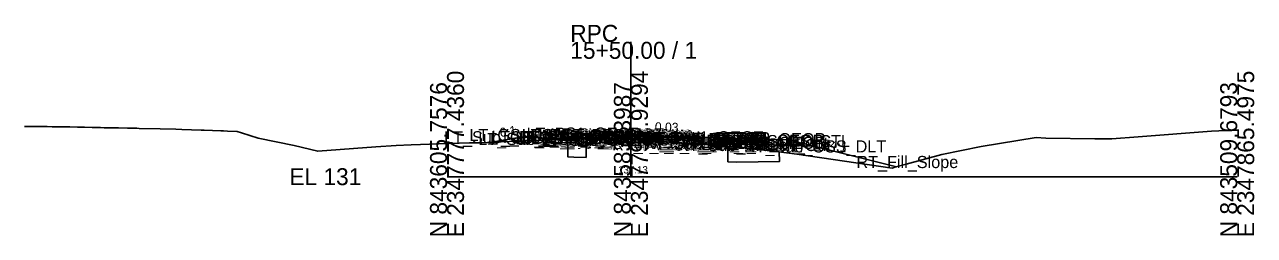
# Model space of a CAD drawing. Extents: x -26 to 203, y -10 to 7538.
# Drawn here: x 0 to 202.8, y 1990.3 to 2025.1 of the extents above; entities that cross this region are included whole.
import ezdxf

# ---------------------------------------------------------------- set-up
doc = ezdxf.new("R2010")
doc.units = 0
for name, color, linetype in [('Default', 7, 'Continuous'), ('Exist CMT Pavement', 7, 'Continuous'), ('Exist Cross Section Cell', 7, 'Continuous'), ('Exist XS Center Line Elevation Label', 7, 'Continuous'), ('Exist XS Ground Line', 7, 'Continuous'), ('Prop CMT Pvmt Course 1', 7, 'Continuous'), ('Prop CMT Pvmt Course 1 Wedge', 7, 'Continuous'), ('Prop CMT Pvmt Course 2', 7, 'Continuous'), ('Prop CMT Pvmt Course 2 Wedge', 7, 'Continuous'), ('Prop CMT Pvmt Course 3', 7, 'Continuous'), ('Prop CMT Pvmt Course 3 Wedge', 7, 'Continuous'), ('Prop CMT Pvmt Surface', 7, 'Continuous'), ('Prop CMT Pvmt Surface Shoulder', 7, 'Continuous'), ('Prop CMT Pvmt Wedge Surface 1', 7, 'Continuous'), ('Prop CMT Pvmt Wedge Surface 2', 7, 'Continuous'), ('Prop CMT Pvmt Wedge Surface 3', 7, 'Continuous'), ('Prop CMT Shld Paved Course 1', 7, 'Continuous'), ('Prop CMT Shld Paved Course 2', 7, 'Continuous'), ('Prop CMT Shld Paved Course 3', 7, 'Continuous'), ('Prop CMT Slope Grass', 7, 'Continuous'), ('Prop CMT Subgrade Earthwork', 7, 'Continuous'), ('Prop Road Sect_ Recs - UC (Outline)', 7, 'Continuous'), ('Prop XS Earthwork Shape', 7, 'Continuous'), ('Prop XS SE Text', 7, 'Continuous'), ('Prop XS Side Slope Text', 7, 'Continuous'), ('Scratch_Level_0', 7, 'Continuous')]:
    doc.layers.add(name, color=color, linetype=linetype)

msp = doc.modelspace()

# ---------------------------------------------------------------- linework, layer by layer
at = {"layer": 'Exist CMT Pavement'}
for q in [(96, 2006.36), (112, 2005.32)]:
    msp.add_line((100, 2006.13), q, dxfattribs=at)
at = {"layer": 'Exist Cross Section Cell'}
for p, q in [((100, 2000), (100, 2022.25)), ((69.67, 2000), (100, 2000)), ((100, 2000), (200, 2000))]:
    msp.add_line(p, q, dxfattribs=at)
at = {"layer": 'Exist XS Ground Line'}
msp.add_lwpolyline([(0, 2008.27), (1.96, 2008.27), (2.8, 2008.27), (3.74, 2008.26), (4.57, 2008.25), (5.33, 2008.24), (6.34, 2008.23), (7.44, 2008.21), (8.75, 2008.18), (9.89, 2008.16), (11.15, 2008.14), (12.5, 2008.09), (13.11, 2008.08), (14.77, 2008.05), (15.15, 2008.04), (15.5, 2008.04), (16.95, 2008.01), (18.52, 2007.98), (18.91, 2007.97), (22.34, 2007.89), (24.93, 2007.83), (25.94, 2007.77), (29.12, 2007.68), (29.61, 2007.66), (32.38, 2007.56), (32.82, 2007.55), (33.44, 2007.5), (35.08, 2007.44), (35.76, 2007.23), (38.55, 2006.36), (44.44, 2005.15), (48.34, 2004.2), (57.91, 2004.91), (61.27, 2005.16), (63.74, 2005.24), (68.35, 2005.43), (73.39, 2005.57), (75.43, 2005.61), (77.3, 2005.68), (86.68, 2006.1), (92.61, 2006.35), (92.97, 2006.35), (93.53, 2006.36), (95.69, 2006.38), (96.47, 2006.33), (96.89, 2006.3), (98.35, 2006.23), (100.26, 2006.12), (103.66, 2005.9), (105.46, 2005.78), (107.09, 2005.66), (107.43, 2005.63), (110.45, 2005.41), (110.97, 2005.38), (112.28, 2005.3), (113.86, 2005.16), (114.27, 2005.13), (115.26, 2005.11), (115.92, 2005.06), (121.74, 2004.41), (123.95, 2004.16), (127.38, 2003.69), (143.07, 2001.4), (143.7, 2001.6), (145.4, 2002.05), (151.3, 2003.68), (157.75, 2004.96), (166.86, 2006.47), (168.43, 2006.36), (176.52, 2006.24), (178.64, 2006.23), (179.3, 2006.26), (183.69, 2006.55), (195.76, 2007.5), (199.39, 2007.66), (200, 2007.7)], dxfattribs=at)
at = {"layer": 'Prop CMT Pvmt Course 1'}
for p, q in [((100, 2006.86), (96, 2006.98)), ((96, 2006.98), (96, 2006.73)), ((96, 2006.73), (96, 2006.86)), ((96, 2006.86), (100, 2006.74)), ((96, 2006.73), (96, 2006.73)), ((100, 2006.61), (100, 2006.86)), ((100, 2006.86), (112, 2006.5)), ((100, 2006.61), (100, 2006.86)), ((100, 2006.74), (100, 2006.61)), ((112, 2006.37), (100, 2006.74)), ((100, 2006.74), (100, 2006.61)), ((100, 2006.61), (100, 2006.61)), ((100, 2006.61), (100, 2006.61)), ((112, 2006.5), (112, 2006.25)), ((112, 2006.25), (112, 2006.37)), ((112, 2006.25), (112, 2006.25))]:
    msp.add_line(p, q, dxfattribs=at)
at = {"layer": 'Prop CMT Pvmt Course 1 Wedge'}
for q in [(96, 2006.86), (112, 2006.37)]:
    msp.add_line((100, 2006.74), q, dxfattribs=at)
at = {"layer": 'Prop CMT Pvmt Course 2'}
for p, q in [((96, 2006.4), (96, 2006.73)), ((96, 2006.73), (96, 2006.73)), ((96, 2006.73), (96, 2006.4)), ((96, 2006.4), (96, 2006.4)), ((112, 2005.91), (112, 2006.25)), ((112, 2006.25), (112, 2006.25)), ((112, 2006.25), (112, 2005.91)), ((112, 2005.91), (112, 2005.91))]:
    msp.add_line(p, q, dxfattribs=at)
at = {"layer": 'Prop CMT Pvmt Course 2 Wedge'}
for q in [(96, 2006.73), (112, 2006.25)]:
    msp.add_line((100, 2006.61), q, dxfattribs=at)
at = {"layer": 'Prop CMT Pvmt Course 3'}
for p, q in [((96, 2006.4), (96, 2006.4)), ((96, 2006.4), (96, 2006.07)), ((96, 2006.07), (96, 2006.4)), ((96, 2006.07), (96, 2006.07)), ((112, 2005.91), (112, 2005.91)), ((112, 2005.91), (112, 2005.58)), ((112, 2005.58), (112, 2005.91)), ((112, 2005.58), (112, 2005.58))]:
    msp.add_line(p, q, dxfattribs=at)
at = {"layer": 'Prop CMT Pvmt Course 3 Wedge'}
for q in [(96, 2006.4), (112, 2005.91)]:
    msp.add_line((100, 2006.28), q, dxfattribs=at)
at = {"layer": 'Prop CMT Pvmt Surface'}
for q in [(96, 2006.98), (112, 2006.5)]:
    msp.add_line((100, 2006.86), q, dxfattribs=at)
at = {"layer": 'Prop CMT Pvmt Surface Shoulder'}
for p, q in [((96, 2006.98), (92, 2007.11)), ((112, 2006.5), (122, 2006.19))]:
    msp.add_line(p, q, dxfattribs=at)
at = {"layer": 'Prop CMT Pvmt Wedge Surface 1'}
for p, q in [((96, 2006.73), (96, 2006.98)), ((100, 2006.74), (96, 2006.86)), ((96, 2006.86), (96, 2006.73)), ((96, 2006.73), (96, 2006.73)), ((100, 2006.74), (112, 2006.37)), ((112, 2006.25), (112, 2006.5)), ((112, 2006.37), (112, 2006.25)), ((112, 2006.25), (112, 2006.25))]:
    msp.add_line(p, q, dxfattribs=at)
at = {"layer": 'Prop CMT Pvmt Wedge Surface 2'}
for p, q in [((96, 2006.73), (96, 2006.98)), ((100, 2006.61), (96, 2006.73)), ((100, 2006.61), (112, 2006.25)), ((112, 2006.25), (112, 2006.5))]:
    msp.add_line(p, q, dxfattribs=at)
at = {"layer": 'Prop CMT Pvmt Wedge Surface 3'}
for p, q in [((96, 2006.4), (96, 2006.98)), ((100, 2006.28), (96, 2006.4)), ((100, 2006.28), (112, 2005.91)), ((112, 2005.91), (112, 2006.5))]:
    msp.add_line(p, q, dxfattribs=at)
at = {"layer": 'Prop CMT Shld Paved Course 1'}
for p, q in [((92, 2007.11), (91.76, 2006.86)), ((91.76, 2006.86), (96, 2006.73)), ((96, 2006.98), (92, 2007.11)), ((96, 2006.73), (96, 2006.98)), ((112, 2006.5), (122, 2006.19)), ((112, 2006.25), (112, 2006.5)), ((122.26, 2005.94), (112, 2006.25)), ((122, 2006.19), (122.26, 2005.94))]:
    msp.add_line(p, q, dxfattribs=at)
at = {"layer": 'Prop CMT Shld Paved Course 2'}
for p, q in [((91.76, 2006.86), (91.43, 2006.54)), ((91.43, 2006.54), (96, 2006.4)), ((96, 2006.73), (91.76, 2006.86)), ((96, 2006.4), (96, 2006.73)), ((112, 2006.25), (122.26, 2005.94)), ((112, 2005.91), (112, 2006.25)), ((122.6, 2005.59), (112, 2005.91)), ((122.26, 2005.94), (122.6, 2005.59))]:
    msp.add_line(p, q, dxfattribs=at)
at = {"layer": 'Prop CMT Shld Paved Course 3'}
for p, q in [((90.93, 2006.55), (90.61, 2006.23)), ((90.61, 2006.23), (96, 2006.07)), ((91.43, 2006.54), (90.93, 2006.55)), ((96, 2006.4), (91.43, 2006.54)), ((96, 2006.07), (96, 2006.4)), ((112, 2005.91), (122.6, 2005.59)), ((112, 2005.58), (112, 2005.91)), ((123.45, 2005.23), (112, 2005.58)), ((122.6, 2005.59), (123.1, 2005.58)), ((123.1, 2005.58), (123.45, 2005.23))]:
    msp.add_line(p, q, dxfattribs=at)
at = {"layer": 'Prop CMT Slope Grass'}
for p, q in [((84, 2006.87), (76.73, 2005.66)), ((92, 2007.11), (84, 2006.87)), ((122, 2006.19), (126, 2006.07)), ((126, 2006.07), (143.8, 2001.62))]:
    msp.add_line(p, q, dxfattribs=at)
at = {"layer": 'Prop CMT Subgrade Earthwork'}
for p, q in [((90.61, 2006.23), (81.78, 2006.5)), ((96, 2006.07), (90.61, 2006.23)), ((96, 2006.07), (96, 2006.36)), ((96, 2006.07), (96, 2006.07)), ((112, 2005.58), (112, 2005.32)), ((112, 2005.58), (123.45, 2005.23)), ((112, 2005.58), (112, 2005.58)), ((123.45, 2005.23), (130.18, 2005.03))]:
    msp.add_line(p, q, dxfattribs=at)
at = {"layer": 'Prop Road Sect_ Recs - UC (Outline)'}
for points in [[(92.61, 2006.17), (92.61, 2003.17), (90.61, 2003.23), (89.61, 2003.26), (89.62, 2006.22), (90.15, 2006.25)], [(116, 2005.05), (116, 2002.46), (117.45, 2002.42), (124.51, 2002.49), (124.48, 2004.09)]]:
    msp.add_lwpolyline(points, close=True, dxfattribs=at)
at = {"layer": 'Prop XS Earthwork Shape'}
for points in [[(76.73, 2005.66), (77.3, 2005.68), (86.68, 2006.1), (90.15, 2006.25), (81.78, 2006.5)], [(90.61, 2006.23), (90.15, 2006.25), (92.61, 2006.35), (92.97, 2006.35), (93.53, 2006.36), (95.69, 2006.38), (96, 2006.36), (96, 2006.07)], [(97.53, 2006.27), (96, 2006.36), (96.47, 2006.33), (96.89, 2006.3)], [(99.97, 2006.13), (97.53, 2006.27), (98.35, 2006.23)], [(100.01, 2006.13), (108.39, 2005.56), (107.43, 2005.63), (107.09, 2005.66), (105.46, 2005.78), (103.66, 2005.9), (100.26, 2006.12)], [(108.39, 2005.56), (110.45, 2005.41), (110.97, 2005.38), (112, 2005.32)], [(130.18, 2005.03), (143.8, 2001.62), (143.7, 2001.6), (143.07, 2001.4), (127.38, 2003.69), (123.95, 2004.16), (121.74, 2004.41), (115.92, 2005.06), (115.26, 2005.11), (114.27, 2005.13), (113.86, 2005.16), (112.28, 2005.3), (112, 2005.32), (112, 2005.58), (123.45, 2005.23)]]:
    msp.add_lwpolyline(points, close=True, dxfattribs=at)

# ---------------------------------------------------------------- texts
at = {"layer": 'Default'}
msp.add_text('-', height=0.0001, dxfattribs=at).set_placement((69.67, 2000))
at = {"layer": 'Exist Cross Section Cell'}
for s, p in [('RPC', (90, 2022.25)), ('15+50.00 / 1', (90, 2019.45)), ('EL 131', (43.67, 1998.6))]:
    msp.add_text(s, height=2.8, dxfattribs=at).set_placement(p)
for s, p in [('E 2347777.4360', (72.47, 1990)), ('E 2347797.9294', (102.8, 1990)), ('E 2347865.4975', (202.8, 1990)), ('N 843605.7576', (69.67, 1990)), ('N 843583.3987', (100, 1990)), ('N 843509.6793', (200, 1990))]:
    msp.add_text(s, height=2.8, rotation=90, dxfattribs=at).set_placement(p)
at = {"layer": 'Exist XS Center Line Elevation Label'}
msp.add_text('137.13', height=1.2, dxfattribs=at).set_placement((97.89, 2000.53))
at = {"layer": 'Prop XS SE Text'}
msp.add_text('0.03', height=1.5, rotation=358.2583, dxfattribs=at).set_placement((103.93, 2007.49))
at = {"layer": 'Prop XS Side Slope Text'}
for s, rotation, p in [('6:1', 9.4623, (78.48, 2006.51)), ('4:1', 345.9638, (132.76, 2004.65))]:
    msp.add_text(s, height=1.5, rotation=rotation, dxfattribs=at).set_placement(p)
at = {"layer": 'Scratch_Level_0'}
for s, p in [('LT_PS1_OEOP', (82.8, 2006.11)), ('LT_Sub_OSS_DLT', (69.19, 2005.5)), ('LT_GS_OS_CTL', (73.37, 2005.87)), ('LT_Sub_Trench_Out', (74.82, 2005.23)), ('LT_PS3_Shelf_Out', (76.92, 2005.55)), ('LT_PV_Sub_Tie_Out', (80.95, 2005.36)), ('LT_PS3_OEOP', (81.67, 2005.54)), ('LT_PS2_OEOP', (81.99, 2005.86)), ('LT_PV_OEEOP_EG', (83.54, 2005.36)), ('LT_Sub_OEEOP', (85.21, 2005.07)), ('LT_PV2_OEEOP', (85.31, 2005.73)), ('LT_PV3_OEEOP', (85.31, 2005.4)), ('LT_PV1_OEEOP', (85.87, 2005.86)), ('LT_Sub_OEOT', (86.08, 2005.07)), ('LT_PV2_OEOT', (86.17, 2005.73)), ('LT_PV3_OEOT', (86.17, 2005.4)), ('LT_PV1_OEOT', (86.74, 2005.98)), ('RT_PV_IEEOP_EG', (88.14, 2005.13)), ('LT_PV_IEEOP_EG', (88.19, 2005.13)), ('RT_PV2_IEEOP', (89.91, 2005.61)), ('RT_PV3_IEEOP', (89.91, 2005.28)), ('LT_PV2_IEEOP', (89.95, 2005.61)), ('LT_PV3_IEEOP', (89.95, 2005.28)), ('RT_PV1_IEEOP', (90.47, 2005.74)), ('LT_PV1_IEEOP', (90.52, 2005.74)), ('PV2_PGL', (93.91, 2005.61)), ('PV1_PGL', (94.47, 2005.86)), ('RT_PV_Sub_Tie_Out', (96.9, 2004.32)), ('RT_PV_OEEOP_EG', (99.49, 2004.32)), ('RT_Sub_OEEOP', (101.17, 2004.58)), ('RT_PV2_OEEOP', (101.26, 2005.25)), ('RT_PV3_OEEOP', (101.26, 2004.91)), ('RT_PV1_OEEOP', (101.83, 2005.37)), ('RT_Sub_OEOT', (102.03, 2004.58)), ('RT_PV2_OEOT', (102.13, 2005.25)), ('RT_PV3_OEOT', (102.13, 2004.91)), ('RT_PV1_OEOT', (102.69, 2005.5)), ('RT_Sub_Trench_Out', (107.6, 2004.23)), ('RT_PS3_Shelf_Out', (109.04, 2004.58)), ('RT_PS2_OEOP', (112.45, 2004.94)), ('RT_PS1_OEOP', (112.76, 2005.19)), ('RT_PS3_OEOP', (112.79, 2004.59)), ('RT_GS_OS_CTL', (115.32, 2004.87)), ('RT_Sub_OSS_DLT', (118.63, 2003.99)), ('RT_Fill_Slope', (137.2, 2001.42))]:
    msp.add_text(s, height=2, dxfattribs=at).set_placement(p)

doc.saveas('drawing.dxf')
